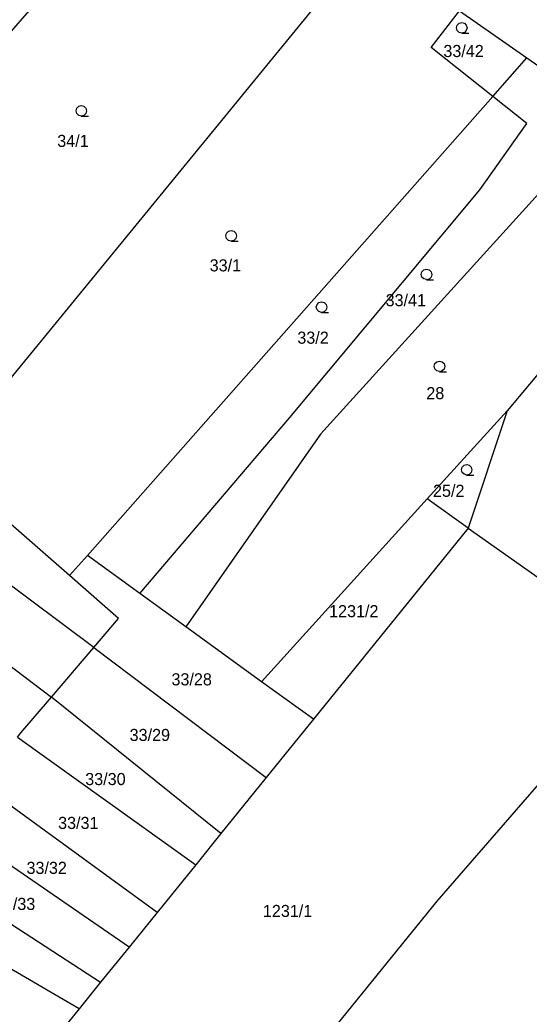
# Model space of a CAD drawing. Extents: x -802857 to -799647, y -1020285 to -1015884.
# Drawn here: x -801573.5 to -801501.8, y -1017921.9 to -1017782.1 of the extents above; entities that cross this region are included whole.
import ezdxf

# ---------------------------------------------------------------- set-up
doc = ezdxf.new("R2010")
doc.units = 0
for name, color, linetype in [('Default', 7, 'Continuous'), ('KN_HRANICE', 7, 'Continuous'), ('KN_KULTURY', 7, 'Continuous'), ('KN_PARCELY', 7, 'Continuous')]:
    doc.layers.add(name, color=color, linetype=linetype)

# ---------------------------------------------------------------- blocks, each defined once
blk = doc.blocks.new('304')
at = {"layer": 'Default'}
blk.add_lwpolyline([(0, 0), (-0.38, 0.1), (-0.65, 0.37), (-0.75, 0.74), (-0.65, 1.11), (-0.38, 1.38), (-0.01, 1.48), (0.36, 1.38), (0.63, 1.11), (0.73, 0.73), (0.63, 0.35), (0.36, 0.08), (-0.02, -0.02), (0.98, -0.02)], dxfattribs=at)

msp = doc.modelspace()

# ---------------------------------------------------------------- linework, layer by layer
at = {"layer": 'KN_HRANICE'}
for p, q in [((-801560.55, -1017767.41), (-801606.93, -1017820.56)), ((-801526.7, -1017773.73), (-801584.65, -1017844.45)), ((-801515.62, -1017785.98), (-801511.62, -1017780.82)), ((-801511.62, -1017780.82), (-801502.15, -1017787.45)), ((-801506.94, -1017792.87), (-801515.62, -1017785.98)), ((-801506.94, -1017792.87), (-801502.15, -1017787.45)), ((-801502.15, -1017787.45), (-801490.56, -1017795.57)), ((-801563.98, -1017857.43), (-801506.94, -1017792.87)), ((-801502.12, -1017796.69), (-801506.94, -1017792.87)), ((-801531.17, -1017840.39), (-801490.56, -1017795.57)), ((-801508.75, -1017806.02), (-801502.12, -1017796.69)), ((-801477.67, -1017804.6), (-801504.93, -1017837.07)), ((-801535.49, -1017838.02), (-801508.75, -1017806.02)), ((-801504.93, -1017837.07), (-801516.16, -1017849.45)), ((-801504.93, -1017837.07), (-801510.41, -1017853.59)), ((-801556.62, -1017862.76), (-801535.49, -1017838.02)), ((-801531.17, -1017840.39), (-801550.13, -1017867.47)), ((-801566.54, -1017860.25), (-801584.65, -1017844.45)), ((-801516.16, -1017849.45), (-801539.5, -1017875.18)), ((-801510.41, -1017853.59), (-801516.16, -1017849.45)), ((-801563.11, -1017870.36), (-801589.67, -1017850.59)), ((-801510.41, -1017853.59), (-801532.16, -1017880.43)), ((-801510.41, -1017853.59), (-801498.22, -1017862.16)), ((-801595.3, -1017857.46), (-801569.08, -1017877.35)), ((-801563.98, -1017857.43), (-801566.54, -1017860.25)), ((-801556.62, -1017862.76), (-801563.98, -1017857.43)), ((-801559.61, -1017866.3), (-801566.54, -1017860.25)), ((-801550.13, -1017867.47), (-801556.62, -1017862.76)), ((-801563.11, -1017870.36), (-801559.61, -1017866.3)), ((-801539.5, -1017875.18), (-801550.13, -1017867.47)), ((-801514.75, -1017906.05), (-801482.86, -1017869.28)), ((-801569.08, -1017877.35), (-801563.11, -1017870.36)), ((-801563.11, -1017870.36), (-801538.82, -1017888.65)), ((-801532.16, -1017880.43), (-801539.5, -1017875.18)), ((-801573.38, -1017882.38), (-801569.08, -1017877.35)), ((-801545.21, -1017896.54), (-801569.08, -1017877.35)), ((-801532.16, -1017880.43), (-801538.82, -1017888.65)), ((-801573.84, -1017882.97), (-801573.38, -1017882.38)), ((-801573.84, -1017882.97), (-801548.75, -1017900.91)), ((-801538.82, -1017888.65), (-801545.21, -1017896.54)), ((-801554.19, -1017907.62), (-801578.98, -1017889.62)), ((-801558.14, -1017912.49), (-801583.31, -1017895.22)), ((-801545.21, -1017896.54), (-801548.75, -1017900.91)), ((-801587.67, -1017900.85), (-801562.14, -1017917.44)), ((-801548.75, -1017900.91), (-801554.19, -1017907.62)), ((-801565.18, -1017921.19), (-801591.49, -1017905.8)), ((-801545.79, -1017944.12), (-801514.75, -1017906.05)), ((-801554.19, -1017907.62), (-801558.14, -1017912.49)), ((-801558.14, -1017912.49), (-801562.14, -1017917.44)), ((-801562.14, -1017917.44), (-801565.18, -1017921.19)), ((-801565.18, -1017921.19), (-801570.17, -1017927.35))]:
    msp.add_line(p, q, dxfattribs=at)

# ---------------------------------------------------------------- block references
at = {"layer": 'KN_KULTURY'}
for p in [(-801511.29, -1017783.97), (-801564.85, -1017795.65), (-801543.76, -1017813.22), (-801516.26, -1017818.64), (-801531.03, -1017823.24), (-801514.43, -1017831.56), (-801510.6, -1017846.11)]:
    msp.add_blockref('304', p, dxfattribs=at)

# ---------------------------------------------------------------- texts
at = {"layer": 'KN_PARCELY'}
for s, p in [('33/42', (-801513.89, -1017787.34)), ('34/1', (-801568.25, -1017799.98)), ('33/1', (-801546.79, -1017817.48)), ('33/41', (-801522.02, -1017822.38)), ('33/2', (-801534.45, -1017827.65)), ('28', (-801516.29, -1017835.45)), ('25/2', (-801515.35, -1017849.18)), ('1231/2', (-801529.98, -1017866.1)), ('33/28', (-801552.17, -1017875.69)), ('33/29', (-801558.06, -1017883.51)), ('33/30', (-801564.31, -1017889.71)), ('33/31', (-801568.13, -1017895.88)), ('33/32', (-801572.58, -1017902.2)), ('33/33', (-801577.03, -1017907.27)), ('1231/1', (-801539.3, -1017908.26))]:
    msp.add_text(s, height=1.7, dxfattribs=at).set_placement(p)

doc.saveas('drawing.dxf')
